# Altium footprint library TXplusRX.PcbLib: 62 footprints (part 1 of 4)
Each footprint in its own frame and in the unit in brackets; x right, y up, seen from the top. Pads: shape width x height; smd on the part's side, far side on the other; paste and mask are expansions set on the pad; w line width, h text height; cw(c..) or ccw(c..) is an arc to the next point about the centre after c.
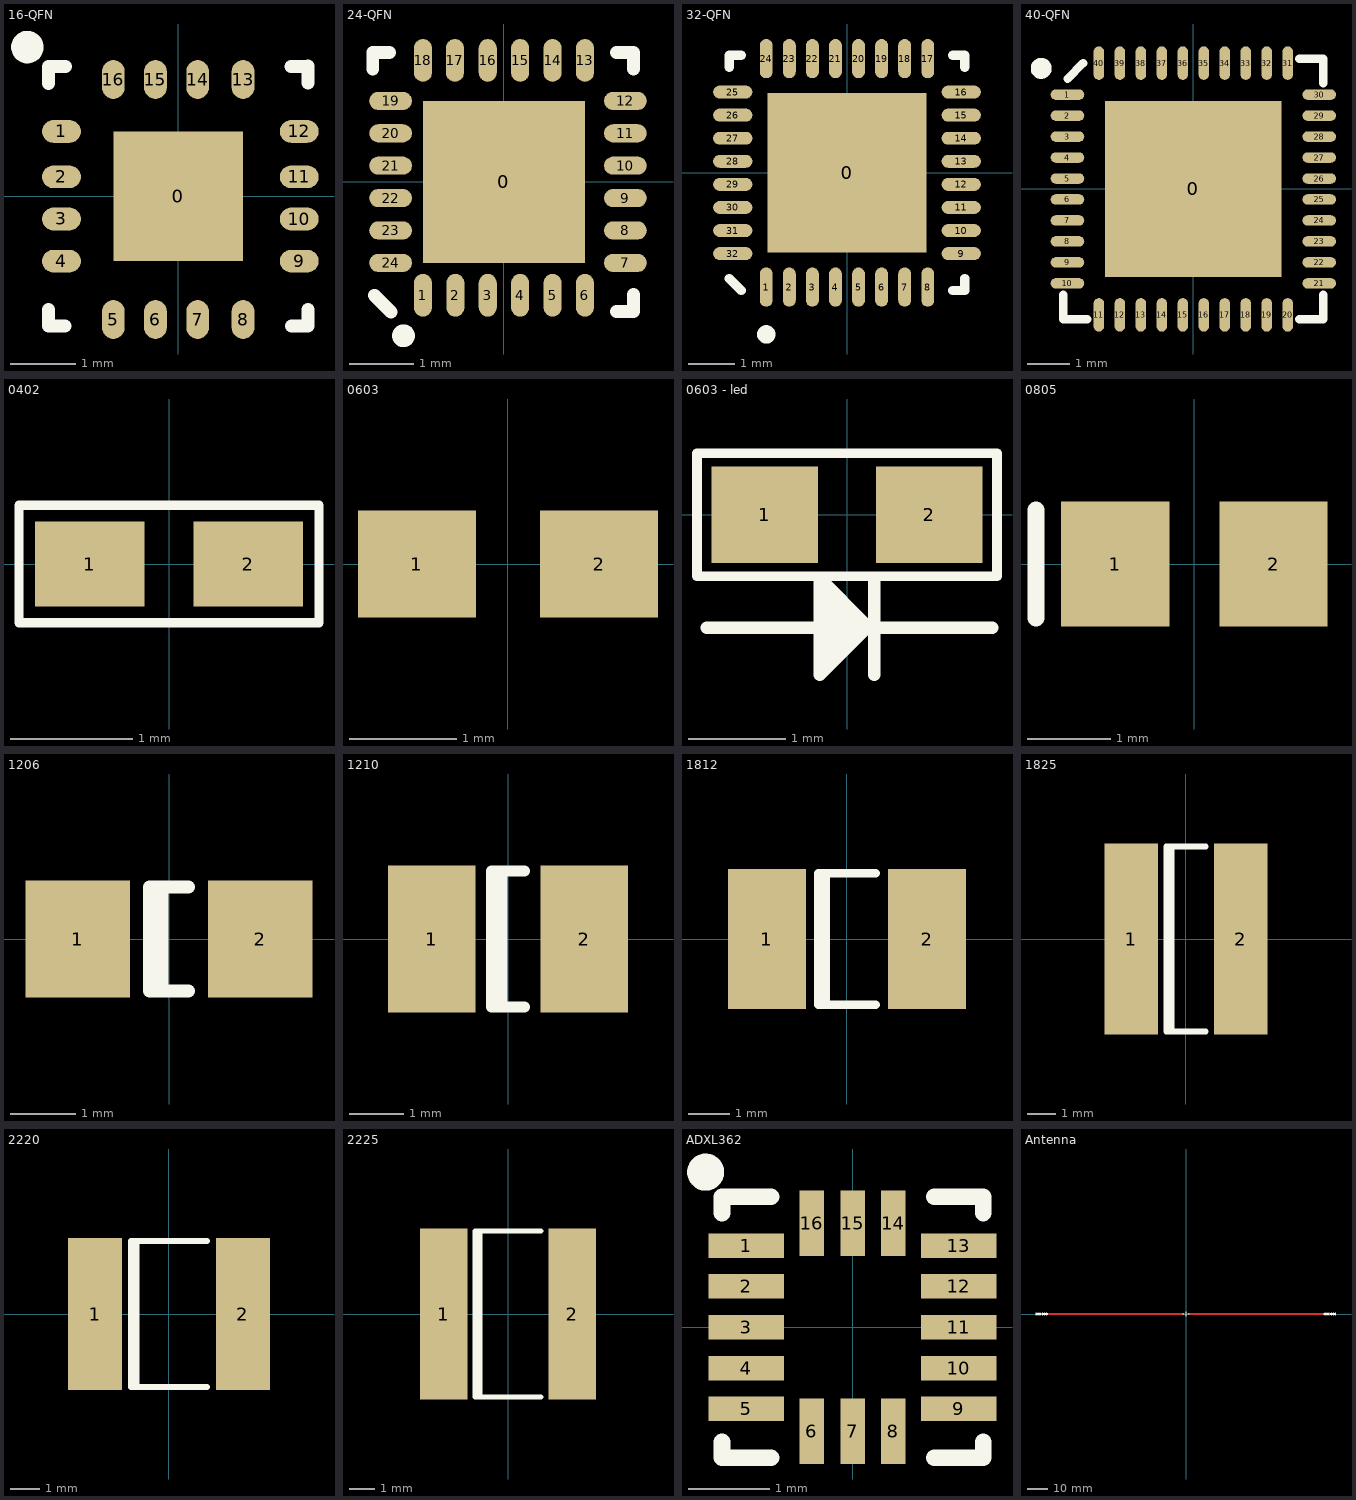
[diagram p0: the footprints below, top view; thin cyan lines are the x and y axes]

## 16-QFN [mm] "16-QFN, LFCSP (CP-16-5) for ADXL330k"
pads (17):
  rect 2x2 smd: 0(0,0)
  oval 0.6x0.35 smd: 1(-1.8,1) 2(-1.8,0.3) 3(-1.8,-0.35) 4(-1.8,-1) 9(1.867,-1) 10(1.867,-0.35) 11(1.867,0.3) 12(1.867,1)
  oval 0.35x0.6 smd: 5(-1,-1.9) 6(-0.35,-1.9) 7(0.3,-1.9) 8(1,-1.9) 13(1,1.8) 14(0.3,1.8) 15(-0.35,1.8) 16(-1,1.8)
Top Overlay:
  circle w0.25: c-2.325,2.3 r0.125
  lines w0.2: -2,-1.746 -2,-2 -1.746,-2 ; -2,1.74 -2,2 -1.74,2 ; 1.74,2 2,2 ; 1.746,-2 2,-2 2,-1.746 ; 2,1.746 2,2.006

## 24-QFN [mm] "24-QFN, for MSP430Fx21x1"
height 1
pads (25):
  rect 2.5x2.5 smd: 0(0,0)
  oval 0.28x0.66 smd: 1(-1.25,-1.75) 2(-0.75,-1.75) 3(-0.25,-1.75) 4(0.25,-1.75) 5(0.75,-1.75) 6(1.25,-1.75) 13(1.25,1.875) 14(0.75,1.875) 15(0.25,1.875) 16(-0.25,1.875) 17(-0.757,1.875) 18(-1.25,1.875)
  oval 0.66x0.28 smd: 7(1.875,-1.25) 8(1.875,-0.75) 9(1.875,-0.25) 10(1.875,0.25) 11(1.875,0.75) 12(1.875,1.25) 19(-1.75,1.25) 20(-1.75,0.75) 21(-1.75,0.25) 22(-1.75,-0.25) 23(-1.75,-0.75) 24(-1.75,-1.25)
Top Overlay:
  circle w0.25: c-1.55,-2.375 r0.05
  lines w0.2: -2.025,1.74 -2.025,2 -1.765,2 ; -2,-1.75 -1.74,-2.01 ; 1.74,-2 2,-2 2,-1.74 ; 1.74,2 2,2 2,1.74

## 32-QFN [mm] "32-QFN, for MSP430F1232"
pads (33):
  rect 3.45x3.45 smd: 0(0,0)
  oval 0.28x0.85 smd: 1(-1.75,-2.475) 2(-1.25,-2.475) 3(-0.75,-2.475) 4(-0.25,-2.475) 5(0.25,-2.475) 6(0.75,-2.475) 7(1.25,-2.475) 8(1.75,-2.475) 17(1.75,2.475) 18(1.25,2.475) 19(0.75,2.475) 20(0.25,2.475) 21(-0.25,2.475) 22(-0.75,2.475) 23(-1.25,2.475) 24(-1.75,2.475)
  oval 0.85x0.28 smd: 9(2.475,-1.75) 10(2.475,-1.25) 11(2.475,-0.75) 12(2.475,-0.25) 13(2.475,0.25) 14(2.475,0.75) 15(2.475,1.25) 16(2.475,1.75) 25(-2.475,1.75) 26(-2.475,1.25) 27(-2.475,0.75) 28(-2.475,0.25) 29(-2.475,-0.25) 30(-2.475,-0.75) 31(-2.475,-1.25) 32(-2.475,-1.75)
Top Overlay:
  circle w0.2: c-1.75,-3.5 r0.1
  lines w0.2: -2.55,-2.29 -2.29,-2.55 ; -2.55,2.29 -2.55,2.55 -2.29,2.55 ; 2.29,-2.55 2.55,-2.55 2.55,-2.29 ; 2.29,2.55 2.55,2.55 2.55,2.29

## 40-QFN [mm] "QFN, 40-Leads, Body 6.2x6.2mm (max), Pitch 0.50mm, IPC Medium Density - MSP430x22x4"
height 1
pads (41):
  rect 4.2x4.2 smd: 0(0,0)
  oval 0.8x0.25 smd: 1(-3,2.25) 2(-3,1.75) 3(-3,1.25) 4(-3,0.75) 5(-3,0.25) 6(-3,-0.25) 7(-3,-0.75) 8(-3,-1.25) 9(-3,-1.75) 10(-3,-2.25) 21(3,-2.25) 22(3,-1.75) 23(3,-1.25) 24(3,-0.75) 25(3,-0.25) 26(3,0.25) 27(3,0.75) 28(3,1.25) 29(3,1.75) 30(3,2.25)
  oval 0.25x0.8 smd: 11(-2.25,-3) 12(-1.75,-3) 13(-1.25,-3) 14(-0.75,-3) 15(-0.25,-3) 16(0.25,-3) 17(0.75,-3) 18(1.25,-3) 19(1.75,-3) 20(2.25,-3) 31(2.25,3) 32(1.75,3) 33(1.25,3) 34(0.75,3) 35(0.25,3) 36(-0.25,3) 37(-0.75,3) 38(-1.25,3) 39(-1.75,3) 40(-2.25,3)
Top Overlay:
  circle w0.25: c-3.625,2.875 r0.125
  lines w0.2: -3.1,-2.525 -3.1,-3.1 -2.525,-3.1 ; -3,2.625 -2.625,3 ; 2.525,-3.1 3.1,-3.1 3.1,-2.525 ; 2.525,3.1 3.1,3.1 3.1,2.525

## 0402 [mm] "Chip Capacitor; Body 1.0 x 0.5 mm (LxW typ)"
height 0.55
pads (2):
  rect 0.9x0.7 smd: 1(-0.65,0) 2(0.65,0)
Top Overlay:
  lines w0.076: -1.232,-0.483 1.232,-0.483 1.232,0.483 -1.232,0.483 -1.232,-0.483

## 0603 [mm] "Chip Capacitor; Body 1.6 x 0.8 mm (LxW typ)"
height 0.87
pads (2):
  rect 1.1x1 smd: 1(-0.85,0) 2(0.85,0)

## 0603 - led [mm] "Chip Capacitor; Body 1.6 x 0.8 mm (LxW typ)"
height 0.87
pads (2):
  rect 1.1x1 smd: 1(-0.85,0) 2(0.85,0)
Top Overlay:
  lines w0.1: -1.549,-0.635 -1.549,0.635 1.549,0.635 1.549,-0.635 -1.549,-0.635
  lines w0.13: -1.448,-1.168 1.499,-1.168 ; 0.203,-1.168 -0.279,-1.651 -0.279,-0.66 0.203,-1.143 ; 0.279,-1.651 0.279,-0.66
  lines w0.254: -0.203,-1.473 0.025,-1.245 0.025,-1.067 -0.178,-0.864 -0.203,-0.864 ; -0.127,-1.346 -0.127,-0.94

## 0805 [mm] "Chip Capacitor; Body 2.0 x 1.2 mm (LxW typ)"
height 1.3
pads (2):
  rect 1.3x1.5 smd: 1(-0.95,0) 2(0.95,0)
Top Overlay:
  lines w0.2: -1.9,-0.65 -1.9,0.65

## 1206 [mm] "Chip Capacitor; Body 3.2 x 1.6 mm (LxW typ)"
height 1.5
pads (2):
  rect 1.6x1.8 smd: 1(-1.4,0) 2(1.4,0)
Top Overlay:
  lines w0.2: -0.11,-0.8 -0.11,0.8 ; 0.3,-0.8 -0.3,-0.8 -0.3,0.8 0.3,0.8

## 1210 [mm] "Chip Capacitor; Body 3.2 x 2.5 mm (LxW typ)"
height 1.7
pads (2):
  rect 1.6x2.7 smd: 1(-1.4,0) 2(1.4,0)
Top Overlay:
  lines w0.2: -0.11,-1.25 -0.11,1.25 ; 0.3,-1.25 -0.3,-1.25 -0.3,1.25 0.3,1.25

## 1812 [mm] "Chip Capacitor; Body 4.5 x 3.2 mm (LxW typ)"
height 1.7
pads (2):
  rect 1.9x3.4 smd: 1(-1.95,0) 2(1.95,0)
Top Overlay:
  lines w0.2: -0.51,-1.6 -0.51,1.6 ; 0.7,-1.6 -0.7,-1.6 -0.7,1.6 0.7,1.6

## 1825 [mm] "Chip Capacitor; Body 4.5 x 6.4 mm (LxW typ)"
height 1.7
pads (2):
  rect 1.9x6.8 smd: 1(-1.95,0) 2(1.95,0)
Top Overlay:
  lines w0.2: -0.51,-3.3 -0.51,3.3 ; 0.7,-3.3 -0.7,-3.3 -0.7,3.3 0.7,3.3

## 2220 [mm] "Chip Capacitor; Body 5.7 x 5.0 mm (LxW typ)"
height 1.8
pads (2):
  rect 1.85x5.2 smd: 1(-2.525,0) 2(2.525,0)
Top Overlay:
  lines w0.2: -1.11,-2.5 -1.11,2.5 ; 1.3,-2.5 -1.3,-2.5 -1.3,2.5 1.3,2.5

## 2225 [mm] "Chip Capacitor; Body 5.6 x 6.4 mm (LxW typ)"
height 2
pads (2):
  rect 1.9x6.8 smd: 1(-2.55,0) 2(2.55,0)
Top Overlay:
  lines w0.2: -1.11,-3.3 -1.11,3.3 ; 1.3,-3.3 -1.3,-3.3 -1.3,3.3 1.3,3.3

## ADXL362 [mm]
pads (16):
  rect 0.925x0.3 smd mask+0.051: 1(-1.3,1) 2(-1.3,0.5) 3(-1.3,0) 4(-1.3,-0.5) 5(-1.3,-1) 9(1.3,-1) 10(1.3,-0.5) 11(1.3,0) 12(1.3,0.5) 13(1.3,1)
  rect 0.3x0.8 smd mask+0.051: 6(-0.5,-1.275) 7(0,-1.275) 8(0.5,-1.275) 14(0.5,1.275) 15(0,1.275) 16(-0.5,1.275)
Top Overlay:
  circle w0.254: c-1.8,1.9 r0.1
  lines w0.203: -1.6,-1.4 -1.6,-1.6 -1,-1.6 ; -1.6,1.4 -1.6,1.6 -1,1.6 ; 1,-1.6 1.6,-1.6 1.6,-1.4 ; 1,1.6 1.6,1.6 1.6,1.4
3D body: height 1.14, standoff 0, extent -1.5,-1.5 1.5,1.5

## Antenna [mm] "915MHz ant used on WIPS 4.0DL"
pads (2):
  round 1 hole 0.6: 1(1.27,0) 2(-1.27,0)
Top Layer:
  region: 72.131,0.5 1.25,0.5 1.25,-0.5 72.131,-0.5
  rectangle: -72.131,-0.5 -1.25,0.5
Top Overlay:
  lines w0.08: -72,-0.5 -72,0.5 ; -71.5,-0.25 -71.5,0.25 ; -71,-0.5 -71,0.5 ; -70.5,-0.25 -70.5,0.25 ; -70,-0.5 -70,0.5 ; -69.5,-0.25 -69.5,0.25 ; -69,-0.5 -69,0.5 ; -68.5,-0.25 -68.5,0.25 ; -68,-0.5 -68,0.5 ; -67.5,-0.25 -67.5,0.25 ; -67,-0.5 -67,0.5 ; -66.5,-0.25 -66.5,0.25 ; 0,-1 0,1 ; 66.5,-0.25 66.5,0.25 ; 67,-0.5 67,0.5 ; 67.5,-0.25 67.5,0.25 ; 68,-0.5 68,0.5 ; 68.5,-0.25 68.5,0.25 ; 69,-0.5 69,0.5 ; 69.5,-0.25 69.5,0.25 ; 70,-0.5 70,0.5 ; 70.5,-0.25 70.5,0.25 ; 71,-0.5 71,0.5 ; 71.5,-0.25 71.5,0.25 ; 72,-0.5 72,0.5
